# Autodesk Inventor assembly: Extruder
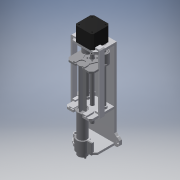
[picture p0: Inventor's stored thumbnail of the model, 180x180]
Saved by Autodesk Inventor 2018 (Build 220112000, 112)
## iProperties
Part Number: Extruder
Material: Genérico
Document SubType Name: Assembly
Designer: ULISES
Author: ULISES
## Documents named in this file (12)
- E:\9 Tecsup\2020 - 1\2 FABLAB\FabAcademy\2_Computer-Aid_Design\FAB_20\Food\Extruder.iam
- E:\9 Tecsup\2020 - 1\2 FABLAB\FabAcademy\2_Computer-Aid_Design\FAB_20\Food\Base_Extruder.ipt
- E:\9 Tecsup\2020 - 1\2 FABLAB\FabAcademy\2_Computer-Aid_Design\FAB_20\Food\Jeringa.ipt
- E:\9 Tecsup\2020 - 1\2 FABLAB\FabAcademy\2_Computer-Aid_Design\FAB_20\Food\Varilla_Ejes.ipt
- E:\9 Tecsup\2020 - 1\2 FABLAB\FabAcademy\2_Computer-Aid_Design\FAB_20\Food\Rodamiento Lineal.ipt
- E:\4 robODIca - Tienda\3 Impresora 3D\1 Diseno\0_ODI_Pieces\1.3_Extrusor_S1_V4.0_ODI_Vent_Late\Motor de Paso.ipt
- E:\9 Tecsup\2020 - 1\2 FABLAB\FabAcademy\2_Computer-Aid_Design\FAB_20\Food\Varilla_Roscada.ipt
- E:\9 Tecsup\2020 - 1\2 FABLAB\FabAcademy\2_Computer-Aid_Design\FAB_20\Food\Inpulsor_Jeringa.ipt
- E:\9 Tecsup\2020 - 1\2 FABLAB\FabAcademy\2_Computer-Aid_Design\FAB_20\Food\Jeringa_Piston.ipt
- E:\9 Tecsup\2020 - 1\2 FABLAB\FabAcademy\2_Computer-Aid_Design\FAB_20\Food\Sujeta_Jeringa.ipt
- E:\4 robODIca - Tienda\5 GRBL - CNC\1 Diseno\0_ODI_Pieces_CNC\Electronica_MiniSwitch.ipt
- E:\9 Tecsup\2020 - 1\2 FABLAB\FabAcademy\2_Computer-Aid_Design\FAB_20\Food\Base_Extruder_Reforzador.ipt
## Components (14 placed, 11 different names)
1. Base_Extruder:1 — Coincidencia:1, Coincidencia:2, Coincidencia:8, Coincidencia:9, Coincidencia:10, Coincidencia:16, Coincidencia:20, Nivelación:3, Coincidencia:21, Coincidencia:23, Coincidencia:24, Coincidencia:25, Coincidencia:26, Coincidencia:27
2. Jeringa:1 — Coincidencia:16, Coincidencia:22, Coincidencia:23
3. Varilla_Ejes:1 — Coincidencia:1, Coincidencia:5, Coincidencia:26
4. Varilla_Ejes:2 — Coincidencia:2, Coincidencia:6, Coincidencia:25
5. Rodamiento Lineal:1 — Coincidencia:5, Coincidencia:13, Nivelación:1
6. Rodamiento Lineal:2 — Coincidencia:6, Coincidencia:14, Nivelación:2
7. Motor de Paso:1 — Coincidencia:8, Coincidencia:9, Coincidencia:10, Coincidencia:11, Coincidencia:12
8. Varilla_Roscada:1 — Coincidencia:11, Coincidencia:12
9. Inpulsor_Jeringa:1 — Coincidencia:13, Nivelación:1, Coincidencia:14, Nivelación:2, Coincidencia:18
10. Jeringa_Piston:1 — Coincidencia:18, Coincidencia:22
11. Sujeta_Jeringa:1 — Coincidencia:20, Nivelación:3, Coincidencia:24
12. Electronica_MiniSwitch:1 — Coincidencia:21, Coincidencia:27
13. Base_Extruder_Reforzador:1
14. Base_Extruder_Reforzador:2
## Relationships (24: Mate 21, Flush 3)
- Coincidencia:1 [Mate]: Base_Extruder:1 ↔ Varilla_Ejes:1
- Coincidencia:2 [Mate]: Base_Extruder:1 ↔ Varilla_Ejes:2
- Coincidencia:5 [Mate]: Varilla_Ejes:1 ↔ Rodamiento Lineal:1
- Coincidencia:6 [Mate]: Varilla_Ejes:2 ↔ Rodamiento Lineal:2
- Coincidencia:8 [Mate]: Base_Extruder:1 ↔ Motor de Paso:1
- Coincidencia:9 [Mate]: Base_Extruder:1 ↔ Motor de Paso:1
- Coincidencia:10 [Mate]: Base_Extruder:1 ↔ Motor de Paso:1
- Coincidencia:11 [Mate]: Motor de Paso:1 ↔ Varilla_Roscada:1
- Coincidencia:12 [Mate]: Motor de Paso:1 ↔ Varilla_Roscada:1
- Coincidencia:13 [Mate]: Rodamiento Lineal:1 ↔ Inpulsor_Jeringa:1
- Nivelación:1 [Flush]: Rodamiento Lineal:1 ↔ Inpulsor_Jeringa:1
- Coincidencia:14 [Mate]: Rodamiento Lineal:2 ↔ Inpulsor_Jeringa:1
- Nivelación:2 [Flush]: Rodamiento Lineal:2 ↔ Inpulsor_Jeringa:1
- Coincidencia:16 [Mate]: Base_Extruder:1 ↔ Jeringa:1
- Coincidencia:18 [Mate]: Inpulsor_Jeringa:1 ↔ Jeringa_Piston:1
- Coincidencia:20 [Mate]: Base_Extruder:1 ↔ Sujeta_Jeringa:1
- Nivelación:3 [Flush]: Base_Extruder:1 ↔ Sujeta_Jeringa:1
- Coincidencia:21 [Mate]: Base_Extruder:1 ↔ Electronica_MiniSwitch:1
- Coincidencia:22 [Mate]: Jeringa:1 ↔ Jeringa_Piston:1
- Coincidencia:23 [Mate]: Base_Extruder:1 ↔ Jeringa:1
- Coincidencia:24 [Mate]: Base_Extruder:1 ↔ Sujeta_Jeringa:1
- Coincidencia:25 [Mate]: Base_Extruder:1 ↔ Varilla_Ejes:2
- Coincidencia:26 [Mate]: Base_Extruder:1 ↔ Varilla_Ejes:1
- Coincidencia:27 [Mate]: Base_Extruder:1 ↔ Electronica_MiniSwitch:1
